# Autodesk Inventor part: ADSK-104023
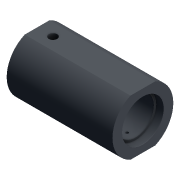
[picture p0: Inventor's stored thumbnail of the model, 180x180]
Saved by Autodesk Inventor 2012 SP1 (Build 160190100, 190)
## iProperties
Shininess: 0.0
Created: 2000-09
Part Number: ADSK-104023
Document SubType Name: Modeling
Stock Number: ADSK-104023
Density: 1 g/cm^3
Material: Default
Density: 0.0
Volumn: 0.0
Area: 0.0
PropertySet Name: Model Information
Control State: 0
Master: False
Checked Out: False
Author: gao
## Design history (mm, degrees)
node "Revolution1" dims "d7" = 360 deg
  sketch "Sketch1"
    geometry: L1 (228.355, 67.438)-(-25.645, 67.438); L2 (-25.645, 67.438)-(-25.645, -5.587); L3 (-25.645, -5.587)-(228.355, -5.587); L4 (228.355, -5.587)-(228.355, 67.438); L5 (-25.645, 49.413)-(-5.645, 49.413); L6 (-5.645, 49.413)-(-5.645, 38.863); L7 (-5.645, 38.863)-(210.355, 38.863); L8 (210.355, 38.863)-(210.355, 44.413); L9 (210.355, 44.413)-(228.355, 44.413)
    constraints: 18 end point, 4 parallel, 4 perpendicular, 2 point on line, 1 horizontal
    dimensions: "d0" = 254 distance of L2.end L3.end; "d1" = 73.025 distance of L1.end L2.end; "d2" = 55 distance between parallel lines of L3 L5; "d3" = 50 distance between parallel lines of L3 L9; "d4" = 44.45 distance between parallel lines of L3 L7; "d5" = 20 distance of L5.start L5.end; "d6" = 18 distance of L8.end L9.end
node "Chamfer1" dims "d8" = 3.175, "d9" = 3.175, "d36" = 45 deg
workplane "Work Plane1"
workplane "Work Plane2"
node "Sketch2"
node "Extrusion1" dims "d10" = 6.35, "d11" = 0
  sketch "Sketch3"
    geometry: L1 (-127, 73.025)-(-127, -73.025) reference; L2 (127, 73.025)-(127, -73.025) reference; L3 (127, 73.025)-(-127, 73.025) reference; L4 (127, -73.025)-(-127, -73.025) reference; L5 (-127, 73.025)-(-127, -73.025); L6 (-123.691, -73.025)-(127, -73.025); L7 (127, -68.289)-(127, 73.025); L8 (127, 73.025)-(-127, 73.025)
    constraints: 8 end point, 3 collinear, 2 point on line, 1 perpendicular
node "Hole1" dims "d13" = 20, "d14" = 9.525, "d15" = 6.35, "d16" = 60 deg, "d17" = 6.35, "d18" = 118 deg
  sketch "Sketch4"
    geometry: L1 (-127, -29.784)-(-127, 29.784) reference; L2 (-127, 73.025)-(127, 73.025) reference; 1 further point
    dimensions: "d12" = 38.1 distance from line of point (-88.9, 0) L1; "d26" = 73.025 distance from line of point (-88.9, 0) L2 (= d1)
workaxis "Work Axis1"
workplane "Work Plane3"
node "Mirror1"
workplane "Work Plane4"
node "Hole3" dims "d29" = 6.4008, "d30" = 9.525, "d31" = 6.35, "d32" = 60 deg, "d33" = 25.4, "d34" = 118 deg, "d35" = 15.875
  sketch "Sketch6"
    geometry: L1 (254, 59.568)-(254, 0) reference; 2 further points
    dimensions: "d27" = 38.1 distance from line of point (215.9, 29.784) L1; "d28" = 63.5 distance of point (152.4, 29.784) point (215.9, 29.784)
body "Solid1"
other parameters: "d25" = 0
